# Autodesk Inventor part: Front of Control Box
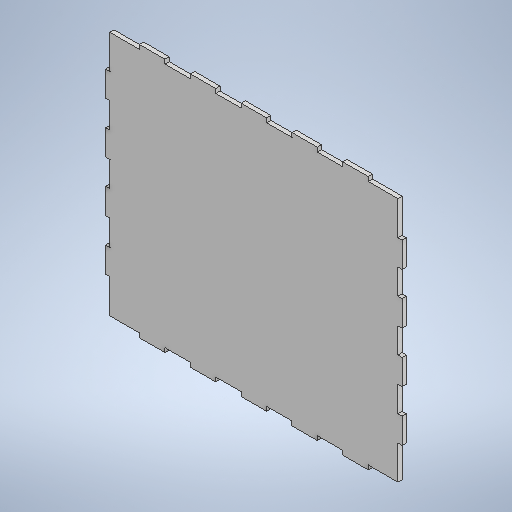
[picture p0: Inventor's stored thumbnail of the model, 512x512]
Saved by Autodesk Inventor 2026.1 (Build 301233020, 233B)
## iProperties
Created: 2026-11
Part Number: Front of Control Box
Material: Generic
Document SubType Name: Modeling
Designer: hp
Density: 1 g/cm^3
Appearance: Default
Author: hp
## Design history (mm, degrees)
sketch "Sketch1"
  geometry: L1 (0, 300)-(350, 300); L2 (350, 300)-(350, 0); L3 (350, 0)-(0, 0); L4 (0, 0)-(0, 300); L5 (190, 0)-(160, 0); L6 (160, 0)-(160, 5); L7 (160, 5)-(190, 5); L8 (190, 5)-(190, 0); L9 (130, 0)-(100, 0); L10 (100, 0)-(100, 5); L11 (100, 5)-(130, 5); L12 (130, 5)-(130, 0); L13 (70, 0)-(40, 0); L14 (40, 0)-(40, 5); L15 (40, 5)-(70, 5); L16 (70, 5)-(70, 0); L17 (250, 0)-(220, 0); L18 (220, 0)-(220, 5); L19 (220, 5)-(250, 5); L20 (250, 5)-(250, 0); L21 (190, 0)-(160, 0); L22 (160, 0)-(160, 5); L23 (160, 5)-(190, 5); L24 (190, 5)-(190, 0); L25 (130, 0)-(100, 0); L26 (100, 0)-(100, 5); L27 (100, 5)-(130, 5); L28 (130, 5)-(130, 0); L29 (310, 0)-(280, 0); L30 (280, 0)-(280, 5); L31 (280, 5)-(310, 5); L32 (310, 5)-(310, 0); L33 (250, 0)-(220, 0); L34 (220, 0)-(220, 5); L35 (220, 5)-(250, 5); L36 (250, 5)-(250, 0); L37 (190, 0)-(160, 0); L38 (160, 0)-(160, 5); L39 (160, 5)-(190, 5); L40 (190, 5)-(190, 0); L41 (350, 150)-(0, 150); L42 (175, 300)-(175, 0); L43 (250, 295)-(250, 300); L44 (250, 300)-(220, 300); L45 (220, 300)-(220, 295); L46 (220, 295)-(250, 295); L47 (190, 295)-(190, 300); L48 (190, 300)-(160, 300); L49 (160, 300)-(160, 295); L50 (160, 295)-(190, 295); L51 (70, 295)-(70, 300); L52 (100, 300)-(100, 295); L53 (100, 295)-(130, 295); L54 (130, 300)-(100, 300); L55 (130, 295)-(130, 300); L56 (70, 300)-(40, 300); L57 (40, 300)-(40, 295); L58 (40, 295)-(70, 295); L59 (280, 295)-(310, 295); L60 (310, 295)-(310, 300); L61 (310, 300)-(280, 300); L62 (280, 300)-(280, 295); L63 (190, 295)-(190, 300); L64 (250, 300)-(220, 300)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; 153 further points
  constraints: 308 end point, 90 symmetric about line, 8 parallel, 6 midpoint, 5 horizontal, 4 perpendicular, 2 vertical, 1 coincident, 1 point on line, 147 other
  dimensions: "d8" = 350 distance of L2.end L3.end; "d9" = 300 distance of L1.end L2.end; "d10" = 30 distance of L6.end L7.end; "d11" = 5 distance of L5.end L6.end; "d12" = 60 distance of L5.start L9.start; "d13" = 60 distance of L5.start L17.start; "d14" = 5 distance of L81.end L80.end; "d15" = 30 distance of L80.end L79.end; "d16" = 60 distance of L79.end L83.end; "d17" = 60 distance of L79.end L91.end; "d18" = 5 distance between parallel lines of L1 L151
extrude "Extrusion1" new body sketch "Sketch1" distance "d19" = 5; taper "d20" = 0 deg
body "Solid1"
node "Sketch Rectangular Pattern2" dims "d12" = 60, "d13" = 60
node "Sketch Rectangular Pattern4" dims "d16" = 60, "d17" = 60
